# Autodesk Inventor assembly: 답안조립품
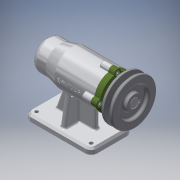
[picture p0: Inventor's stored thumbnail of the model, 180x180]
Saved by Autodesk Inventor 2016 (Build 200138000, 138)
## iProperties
Created: 2019-07
Part Number: 답안조립품
Material: 일반
Document SubType Name: Assembly
Designer: 605-06
Author: 605-06
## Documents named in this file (12)
- C:\Users\605-06\Desktop\490704V1011\답안조립품.iam
- C:\Users\605-06\Desktop\490704V1011\본체.ipt
- C:\Users\605-06\Desktop\490704V1011\V벨트풀리.ipt
- C:\Users\605-06\Desktop\490704V1011\멈춤나사 M3.ipt
- C:\Users\605-06\Desktop\490704V1011\베어링 6004.ipt
- C:\Users\605-06\Desktop\490704V1011\베어링 51202.ipt
- C:\Users\605-06\Desktop\490704V1011\볼트 M4.ipt
- C:\Users\605-06\Desktop\490704V1011\어댑터슬리브.ipt
- C:\Users\605-06\Desktop\490704V1011\오일 실.ipt
- C:\Users\605-06\Desktop\490704V1011\축.ipt
- C:\Users\605-06\Desktop\490704V1011\커버.ipt
- C:\Users\605-06\Desktop\490704V1011\키 5 x 5 x 16.ipt
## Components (1 placed, 1 different names)
1. V벨트풀리:1
